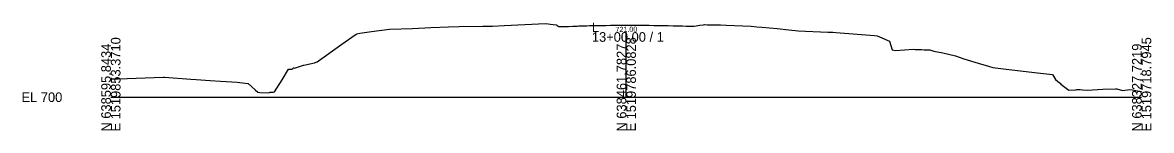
# Model space of a CAD drawing. Extents: x -26 to 3903, y -10 to 9531.
# Drawn here: x -25.7 to 302.8, y 2990.3 to 3021.8 of the extents above; entities that cross this region are included whole.
import ezdxf

# ---------------------------------------------------------------- set-up
doc = ezdxf.new("R2010")
doc.units = 0
for name, color, linetype in [('Default', 7, 'Continuous'), ('Exist Cross Section Cell', 7, 'Continuous'), ('Exist XS Center Line Elevation Label', 7, 'Continuous'), ('Exist XS Ground Line', 7, 'Continuous')]:
    doc.layers.add(name, color=color, linetype=linetype)

msp = doc.modelspace()

# ---------------------------------------------------------------- linework, layer by layer
at = {"layer": 'Exist Cross Section Cell'}
for p, q in [((150, 3000), (150, 3018.96)), ((0, 3000), (150, 3000)), ((150, 3000), (300, 3000))]:
    msp.add_line(p, q, dxfattribs=at)
at = {"layer": 'Exist XS Ground Line'}
msp.add_lwpolyline([(0, 3005.34), (0.41, 3005.35), (2.13, 3005.37), (15.2, 3005.84), (15.66, 3005.81), (23.26, 3005.26), (24.84, 3005.12), (28.94, 3004.88), (31.87, 3004.65), (35.18, 3004.48), (36.78, 3004.39), (39.91, 3003.96), (39.98, 3003.95), (40, 3003.95), (40, 3003.95), (41.97, 3002.16), (41.98, 3002.14), (42.79, 3001.45), (42.8, 3001.44), (43.32, 3001.33), (43.33, 3001.32), (43.37, 3001.33), (45.94, 3001.32), (45.94, 3001.32), (46.38, 3001.42), (46.39, 3001.42), (47.27, 3001.5), (47.66, 3001.54), (49.81, 3005.09), (51.67, 3008.2), (52.68, 3008.21), (52.96, 3008.32), (53.17, 3008.53), (53.26, 3008.57), (53.48, 3008.51), (56.1, 3009.31), (56.13, 3009.32), (59.27, 3010.05), (60.01, 3010.35), (67.19, 3015.43), (71.08, 3018.14), (71.63, 3018.52), (72.5, 3018.64), (75.88, 3019.16), (81.11, 3019.81), (87.8, 3020.07), (93.09, 3020.29), (98.26, 3020.49), (101.34, 3020.65), (108.24, 3020.7), (109.94, 3020.71), (111.07, 3020.7), (114.47, 3020.89), (126.54, 3021.45), (128.73, 3021.18), (129.74, 3021.07), (129.92, 3020.93), (130.36, 3020.57), (131.31, 3020.6), (132.2, 3020.62), (132.9, 3020.64), (133.16, 3020.65), (134.43, 3020.7), (135.69, 3020.75), (136.19, 3020.77), (137.16, 3020.8), (138.5, 3020.84), (139.3, 3020.87), (139.54, 3020.88), (139.61, 3020.88), (141.29, 3020.89), (142.73, 3020.91), (144.07, 3020.94), (145.45, 3020.96), (146.87, 3020.98), (147.34, 3020.99), (148.28, 3020.99), (149.48, 3021), (149.71, 3021.01), (150.02, 3021.01), (151.07, 3021), (152.48, 3021.01), (153.87, 3021), (154.8, 3020.99), (155.26, 3020.99), (156.65, 3020.96), (158.06, 3020.93), (158.87, 3020.92), (159.93, 3020.92), (160.37, 3020.9), (160.84, 3020.89), (162.23, 3020.86), (163.65, 3020.83), (164.1, 3020.82), (164.98, 3020.8), (166.4, 3020.76), (167.42, 3020.74), (168.04, 3020.71), (169.36, 3020.69), (169.74, 3020.68), (171.38, 3020.95), (172.47, 3021.13), (172.73, 3021.18), (173.59, 3021.11), (177.46, 3021.09), (179.11, 3021.02), (186.35, 3020.66), (187.97, 3020.49), (189.45, 3020.4), (193.9, 3020.04), (197.28, 3019.66), (200.03, 3019.35), (208.66, 3019), (209.73, 3018.96), (210.1, 3018.94), (211, 3018.9), (222.24, 3017.99), (223.05, 3017.87), (223.68, 3017.58), (226.64, 3016.31), (227.42, 3013.81), (228.34, 3013.63), (233.63, 3013.98), (234.12, 3013.94), (235.97, 3013.94), (236.74, 3013.81), (237.52, 3013.84), (238.34, 3013.76), (239.53, 3013.4), (242.15, 3012.92), (245.8, 3012.04), (248.25, 3011.19), (252.38, 3009.95), (255.46, 3009), (256.66, 3008.66), (259.79, 3008.25), (262.22, 3007.94), (269.72, 3007.07), (274.01, 3006.58), (274.93, 3005.15), (276.05, 3004.16), (276.24, 3004.12), (276.43, 3003.8), (276.47, 3003.81), (278.85, 3002.08), (280.82, 3002.18), (281.18, 3002.21), (282.1, 3002.24), (282.81, 3002.19), (284.15, 3002.07), (288.7, 3002.32), (292.41, 3002.45), (292.77, 3002.46), (294.46, 3001.91), (296.55, 3002.27), (297.21, 3002.11), (298.83, 3001.82), (299.17, 3001.75), (299.85, 3001.63), (300, 3001.6)], dxfattribs=at)

# ---------------------------------------------------------------- texts
at = {"layer": 'Default'}
msp.add_text('-', height=0.0001, dxfattribs=at).set_placement((0, 3000))
at = {"layer": 'Exist Cross Section Cell'}
for s, p in [('L', (140, 3018.96)), ('13+00.00 / 1', (140, 3016.16)), ('EL 700', (-26, 2998.6))]:
    msp.add_text(s, height=2.8, dxfattribs=at).set_placement(p)
for s, p in [('E 1519853.3710', (2.8, 2990)), ('E 1519786.0828', (152.8, 2990)), ('E 1519718.7945', (302.8, 2990)), ('N 638595.8434', (0, 2990)), ('N 638461.7827', (150, 2990)), ('N 638327.7219', (300, 2990))]:
    msp.add_text(s, height=2.8, rotation=90, dxfattribs=at).set_placement(p)
at = {"layer": 'Exist XS Center Line Elevation Label'}
msp.add_text('721.00', height=1.5, rotation=0.8401, dxfattribs=at).set_placement((146.87, 3018.99))

doc.saveas('drawing.dxf')
